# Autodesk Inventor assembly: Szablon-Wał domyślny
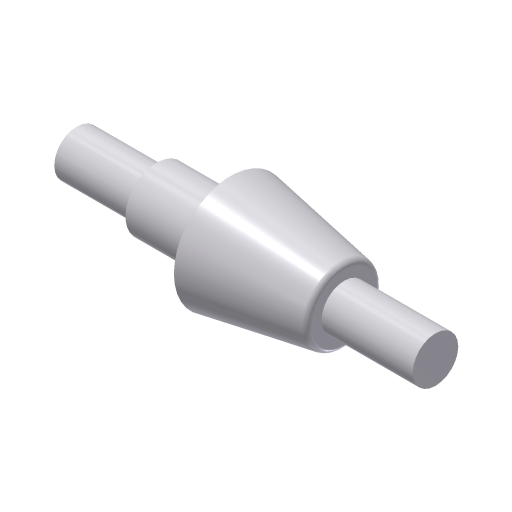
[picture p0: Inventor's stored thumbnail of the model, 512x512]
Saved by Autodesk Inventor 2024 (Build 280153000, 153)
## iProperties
Company: ATC
Created: 2023-03
Part Number: Szablon-Wał domyślny
Document SubType Name: Assembly
Designer: Andrzej Jaskulski
Checked By: A.J.
Engr Approved By: Andrzej Jaskulski
Mfg Approved By: Andrzej Jaskulski
Authority: A.J.
Author: Andrzej Jaskulski
Title: A.J.: Kurs R2024-MEP
Revision Number: 1/24
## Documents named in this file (2)
- C:\Users\AndJas\Documents\R2024-MEP\Obszar roboczy\PZ\Szablon-Wał domyślny.iam
- C:\Users\AndJas\Documents\R2024-MEP\Obszar roboczy\PZ\Szablon-Wał domyślny\ContentCenter\Szablon-Wał domyślny-WAŁ1.iam
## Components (1 placed, 1 different names)
1. Wał:1 [sub-assembly]
